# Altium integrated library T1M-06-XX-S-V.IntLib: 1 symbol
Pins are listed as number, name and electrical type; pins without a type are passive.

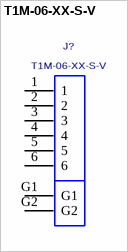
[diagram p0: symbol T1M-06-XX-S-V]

## T1M-06-XX-S-V
designator J?
1MM TERMINAL STRIP, 6 PINS.; MANUFACTURER: SAMTEC
footprint T1M-06-XX-S-V
pins: 1, 2, 3, 4, 5, 6, G1, G2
